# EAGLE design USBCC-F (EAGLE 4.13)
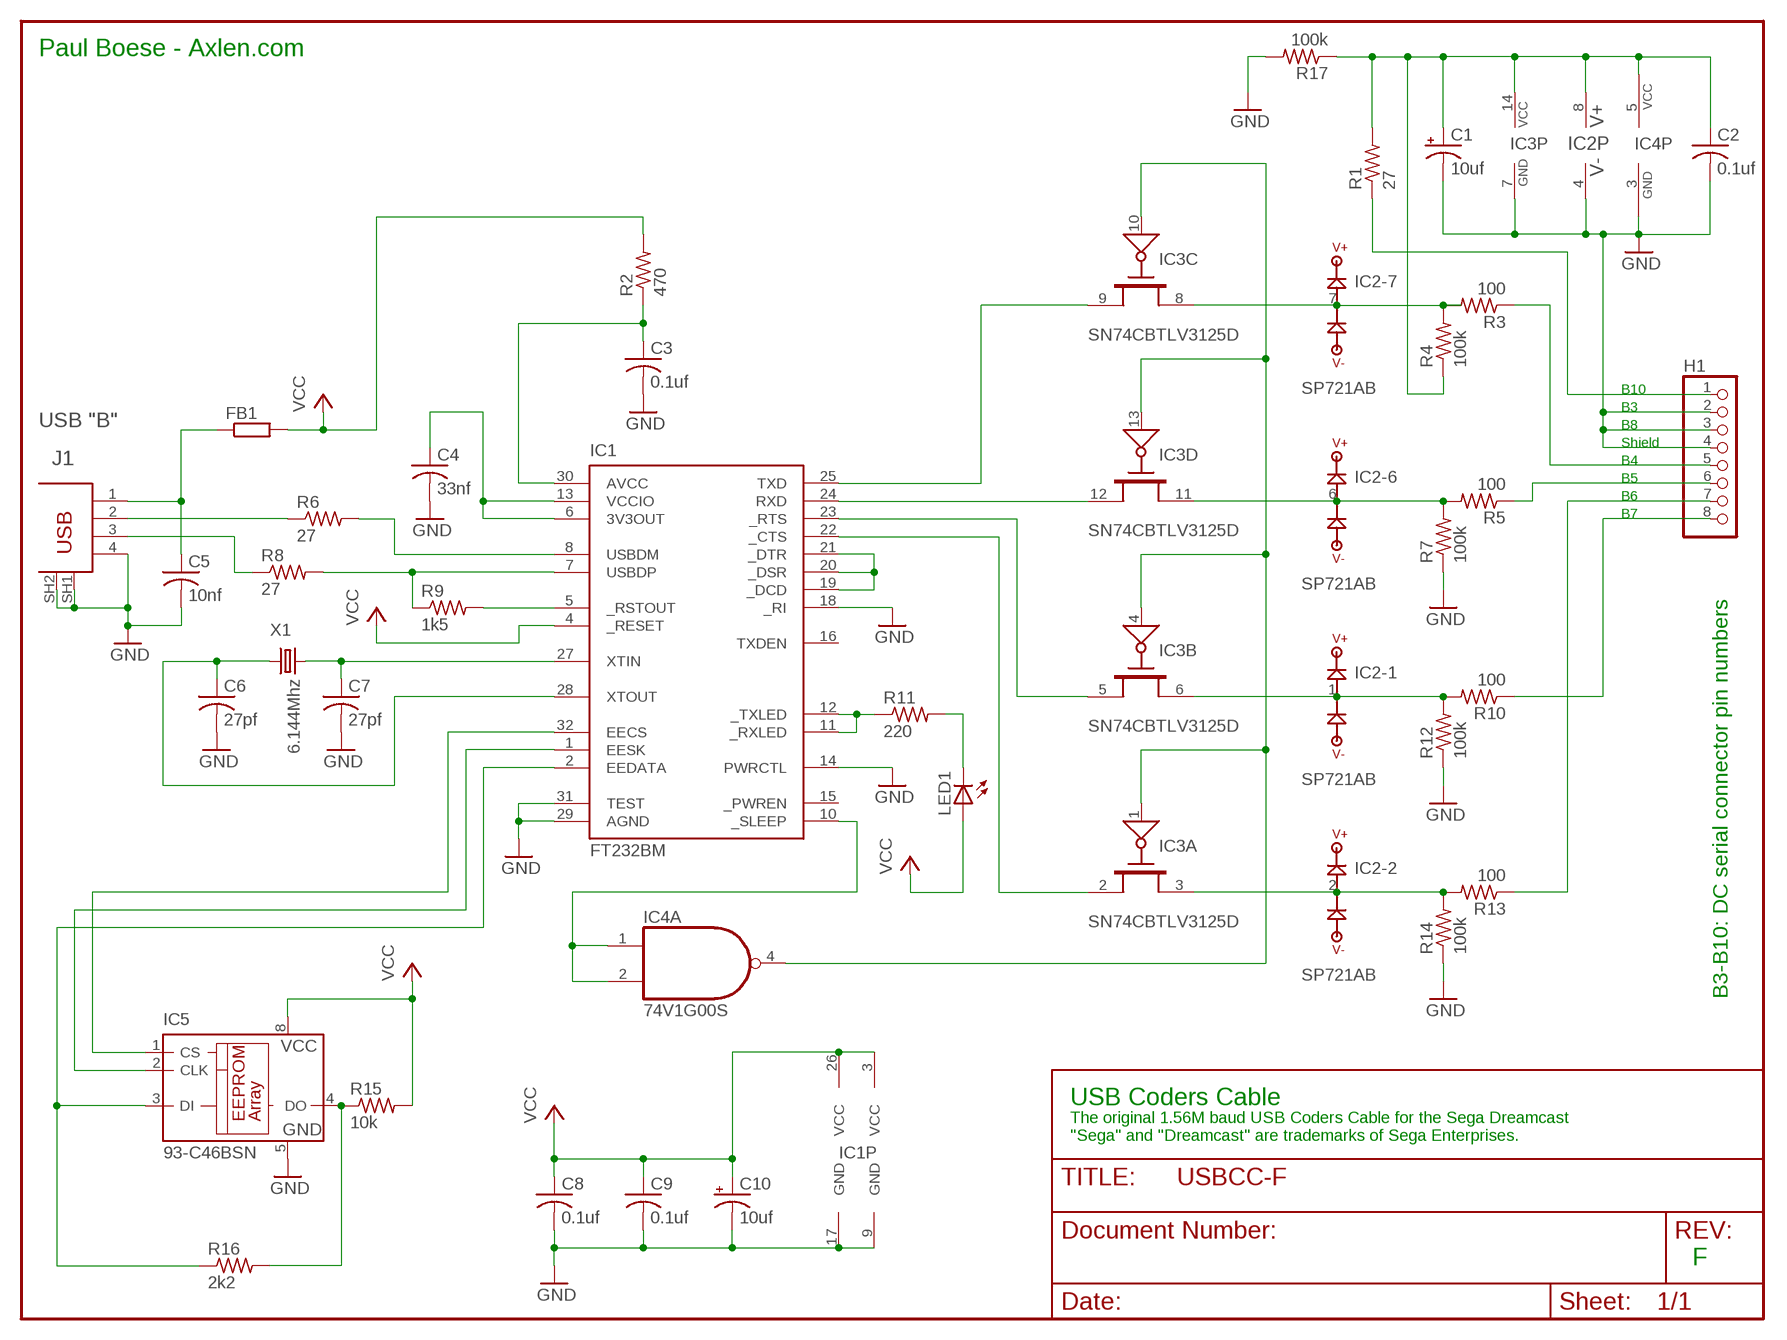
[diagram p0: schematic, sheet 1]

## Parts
C1  10uf  CPOL-USB/3528-21R  [B/3528-21R]
C2  0.1uf  C-USC0805  [C0805]
C3  0.1uf  C-USC0805  [C0805]
C4  33nf  C-USC0805  [C0805]
C5  10nf  C-USC0805  [C0805]
C6  27pf  C-USC0805  [C0805]
C7  27pf  C-USC0805  [C0805]
C8  0.1uf  C-USC0805  [C0805]
C9  0.1uf  C-USC0805  [C0805]
C10  10uf  CPOL-USB/3528-21R  [B/3528-21R]
FB1  R-EU_R0805  [R0805]
H1  PINHD-1X8  [1X08]
IC1  FT232BM  [LQFP-32]
IC2  SP721AB  [SO08]
IC3  SN74CBTLV3125D  74CBTLV125D  [SO14]
IC4  74V1G00S  [SOT23-5]
IC5  93-C46BSN  [SO-08]
J1  USB "B"  PN61729S  [PN61729]
LED1  LED5MM  [LED5MM]
R1  27  R-US_R0805  [R0805]
R2  470  R-US_R0805  [R0805]
R3  100  R-US_R0805  [R0805]
R4  100k  R-US_R0805  [R0805]
R5  100  R-US_R0805  [R0805]
R6  27  R-US_R0805  [R0805]
R7  100k  R-US_R0805  [R0805]
R8  27  R-US_R0805  [R0805]
R9  1k5  R-US_R0805  [R0805]
R10  100  R-US_R0805  [R0805]
R11  220  R-US_R1206  [R1206]
R12  100k  R-US_R0805  [R0805]
R13  100  R-US_R0805  [R0805]
R14  100k  R-US_R0805  [R0805]
R15  10k  R-US_R0805  [R0805]
R16  2k2  R-US_R0805  [R0805]
R17  100k  R-US_R0805  [R0805]
X1  6.144Mhz  CRYTALHC49U-V  [HC49U-V]

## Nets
GND: C1.- C2.2 C3.2 C4.2 C5.2 C6.2 C7.2 C8.2 C9.2 C10.- H1.2 H1.3 H1.4 IC1.9(GND) IC1.14(PWRCTL) IC1.17(GND) IC1.18(_RI) IC1.29(AGND) IC1.31(TEST) IC2.4(P:V-) IC3.7(P:GND) IC4.3(P:GND) IC5.5(GND) J1.4 J1.SH1 J1.SH2 R7.1 R12.1 R14.1 R17.2
N$2: J1.3 R8.1
N$3: IC1.7(USBDP) R8.2 R9.1
N$4: IC1.5(_RSTOUT) R9.2
N$5: IC1.8(USBDM) R6.2
N$6: C5.1 FB1.1 J1.1
N$7: C7.1 IC1.27(XTIN) X1.2
N$8: C3.1 IC1.30(AVCC) R2.1
N$9: C6.1 IC1.28(XTOUT) X1.1
N$10: IC1.24(RXD) IC3.12(D:I)
N$11: IC1.11(_RXLED) IC1.12(_TXLED) R11.1
N$13: IC5.4(DO) R15.1 R16.2
N$14: IC1.19(_DCD) IC1.20(_DSR) IC1.21(_DTR)
N$15: IC1.25(TXD) IC3.9(C:I)
N$17: C4.1 IC1.6(3V3OUT) IC1.13(VCCIO)
N$18: LED1.K(C) R11.2
N$19: IC1.2(EEDATA) IC5.3(DI) R16.1
N$20: IC1.23(_RTS) IC3.5(B:I)
N$21: IC1.22(_CTS) IC3.2(A:I)
N$22: C1.+ C2.1 IC2.8(P:V+) IC3.14(P:VCC) IC4.5(P:VCC) R1.2 R4.1 R17.1
N$24: IC2.7(-7:IN) IC3.8(C:O) R3.2 R4.2
N$26: IC2.6(-6:IN) IC3.11(D:O) R5.2 R7.2
N$27: H1.6 R5.1
N$28: H1.8 R10.1
N$29: H1.7 R13.1
N$32: H1.1 R1.1
N$34: H1.5 R3.1
N$35: IC2.1(-1:IN) IC3.6(B:O) R10.2 R12.2
N$36: IC2.2(-2:IN) IC3.3(A:O) R13.2 R14.2
N$37: IC1.1(EESK) IC5.2(CLK)
N$38: IC3.1(A:OE) IC3.4(B:OE) IC3.10(C:OE) IC3.13(D:OE) IC4.4(A:O)
N$39: IC1.32(EECS) IC5.1(CS)
N$40: IC1.10(_SLEEP) IC4.1(A:I0) IC4.2(A:I1)
N$41: J1.2 R6.1
VCC: C8.1 C9.1 C10.+ FB1.2 IC1.3(VCC) IC1.4(_RESET) IC1.26(VCC) IC5.8(VCC) LED1.A R2.2 R15.2
Unconnected: IC1.15(_PWREN) IC1.16(TXDEN) IC2.3(-3:IN) IC2.5(-5:IN)

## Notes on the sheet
- Paul Boese - Axlen.com
- B10
- B3
- B8
- Shield
- B4
- B5
- B6
- B7
- B3-B10: DC serial connector pin numbers
- USB Coders Cable
- The original 1.56M baud USB Coders Cable for the Sega Dreamcast
- "Sega" and "Dreamcast" are trademarks of Sega Enterprises.
- F

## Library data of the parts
C1 C10 = rcl:CPOL-US: POLARIZED CAPACITOR, American symbol
C2-C9 = rcl:C-US: CAPACITOR, American symbol
FB1 = rcl:R-EU_: RESISTOR, European symbol
H1 = pinhead:PINHD-1X8: PIN HEADER
IC1 = ftdi:FT232BM: USB UART 2nd Generation USB UART (USB <-> Serial)
IC2 = littelfuse:SP721: SP721 - TVS Diode Array Transient Voltage Suppressor 6 per package
IC3 = boese:74*125: Quad BUS SWITCH
IC4 = boese:74V1G00: Quad 2-input NAND gate
IC5 = microchip:93-*: Serial EEPROM 512 x 8 bit/256 x 16 bit/1 K/4 K, 5.0 V, Microwire
J1 = con-berg:PN61729S
LED1 = led:LED: LED
R1-R17 = rcl:R-US_: RESISTOR, American symbol
X1 = crystal:CRYTAL: CRYSTAL

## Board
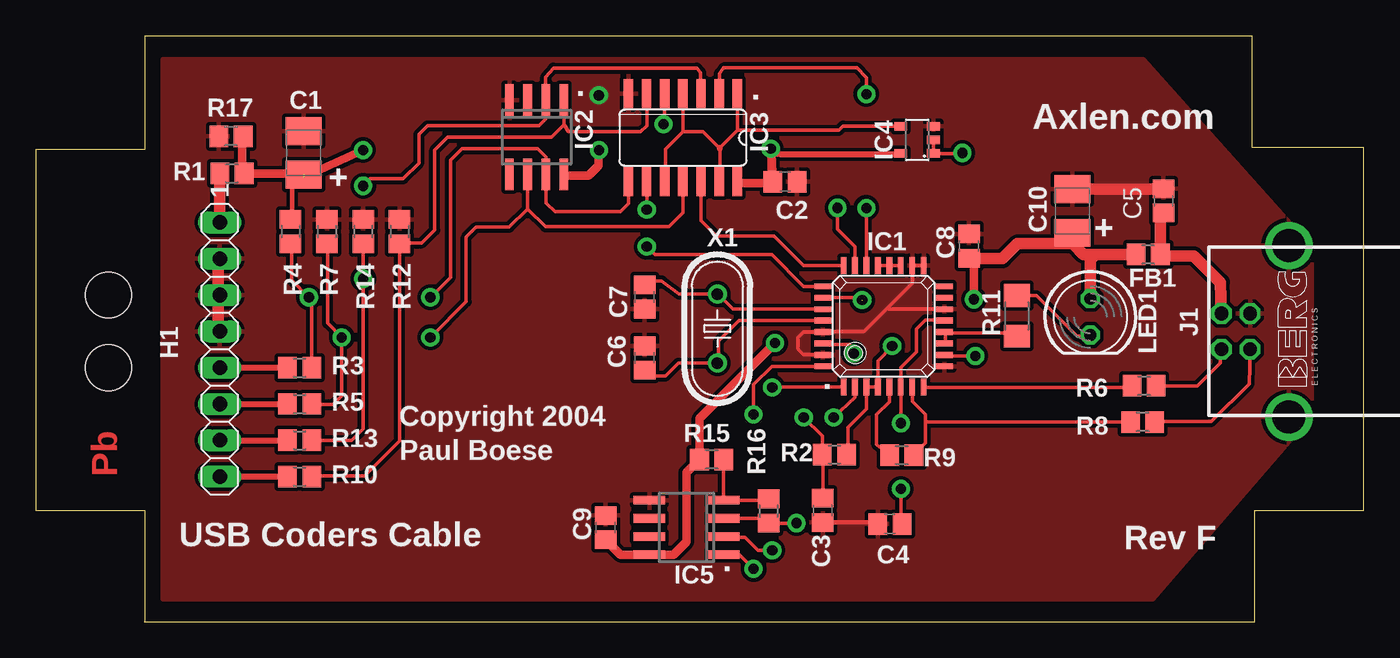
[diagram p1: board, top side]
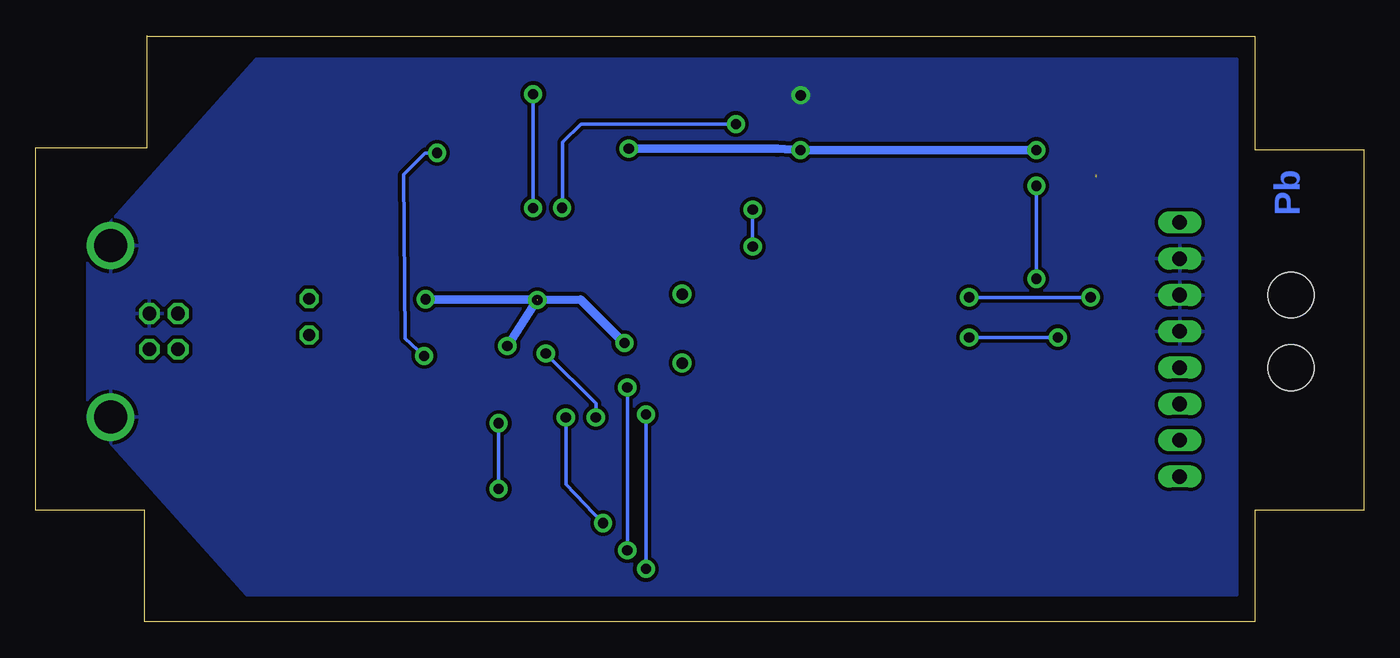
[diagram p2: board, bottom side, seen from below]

Size 92.87 x 41 mm. Coordinates in mm from the lower left corner, seen from the top.
Outline: 7.58,0 85.25,0 85.25,7.78 92.87,7.78 92.87,33.18 85.09,33.18 85.06,41
Outline: 85.06,40.96 7.62,40.96 7.62,33.02 0,33.02 0,7.78 7.62,7.78 7.62,0
Copper layers (1*16): Top 0.035mm / dielectric 1.5mm / Bottom 0.035mm
Design rules "default": minimum track width 10mil, minimum drill 28mil, track to track 10mil, track to pad 10mil, pad to pad 10mil, via to via 10mil, smd to smd 8mil, copper to edge 40mil, drill to drill 10mil, minimum pad ring 10mil, minimum via ring 8mil, stop-mask expansion 4mil, vias tented up to drill 0mil, thermal gap 10mil
Holes 3.2 mm at 5.08,22.86 5.08,17.78

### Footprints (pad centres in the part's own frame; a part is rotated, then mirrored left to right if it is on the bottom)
B/3528-21R = smd 1.95 x 2.5: + 1.525,0; - -1.525,0
C0805 = smd 1.3 x 1.5: 1 -0.85,0; 2 0.85,0
R0805 = smd 1.3 x 1.5: 1 -0.85,0; 2 0.85,0
1X08 = drill 1.016 long: 1 -8.89,0; 2 -6.35,0; 3 -3.81,0; 4 -1.27,0; 5 1.27,0; 6 3.81,0; 7 6.35,0; 8 8.89,0
LQFP-32 = smd 0.4 x 1.2: 1 -2.8,-4.25; 2 -2,-4.25; 3 -1.2,-4.25; 4 -0.4,-4.25; 5 0.4,-4.25; 6 1.2,-4.25; 7 2,-4.25; 8 2.8,-4.25; 17 2.8,4.25; 18 2,4.25; 19 1.2,4.25; 20 0.4,4.25; 21 -0.4,4.25; 22 -1.2,4.25; 23 -2,4.25; 24 -2.8,4.25 | smd 1.2 x 0.4: 9 4.25,-2.8; 10 4.25,-2; 11 4.25,-1.2; 12 4.25,-0.4; 13 4.25,0.4; 14 4.25,1.2; 15 4.25,2; 16 4.25,2.8; 25 -4.25,2.8; 26 -4.25,2; 27 -4.25,1.2; 28 -4.25,0.4; 29 -4.25,-0.4; 30 -4.25,-1.2; 31 -4.25,-2; 32 -4.25,-2.8
SO08 = smd 0.6 x 2.2: 1 -1.905,-2.6; 2 -0.635,-2.6; 3 0.635,-2.6; 4 1.905,-2.6; 5 1.905,2.6; 6 0.635,2.6; 7 -0.635,2.6; 8 -1.905,2.6
SO14 = smd 0.66 x 2.032: 1 -3.81,-3.073; 2 -2.54,-3.073; 3 -1.27,-3.073; 4 0,-3.073; 5 1.27,-3.073; 6 2.54,-3.073; 7 3.81,-3.073; 8 3.81,3.073; 9 2.54,3.073; 10 1.27,3.073; 11 0,3.073; 12 -1.27,3.073; 13 -2.54,3.073; 14 -3.81,3.073
SOT23-5 = smd 0.6 x 0.9: 1 -0.95,-1.15; 2 0,-1.15; 3 0.95,-1.15; 4 0.95,1.15; 5 -0.95,1.15
SO-08 = smd 0.6 x 2.2: 1 -1.905,-2.6; 2 -0.635,-2.6; 3 0.635,-2.6; 4 1.905,-2.6; 5 1.905,2.6; 6 0.635,2.6; 7 -0.635,2.6; 8 -1.905,2.6
PN61729 = drill 0.95 octagon: 1 1.25,4.71; 2 -1.25,4.71; 3 -1.25,2.71; 4 1.25,2.71 | drill 2.3 round: SH1 -6,0; SH2 6,0
LED5MM = drill 0.813 octagon: A -1.27,0; K 1.27,0
R1206 = smd 1.6 x 1.803: 1 -1.422,0; 2 1.422,0
HC49U-V = drill 0.813 round: 1 -2.413,0; 2 2.413,0

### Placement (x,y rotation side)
C1  18.73,32.81 270 top
C2  52.39,30.78 0 top
C3  55.04,7.8 270 top
C4  59.73,6.84 180 top
C5  78.87,29.45 90 top
C6  42.59,18.45 90 top
C7  42.59,22.73 270 top
C8  65.27,26.29 90 top
C9  39.86,6.59 90 top
C10  72.5,28.74 270 top
FB1  77.79,25.7 180 top
H1  12.87,19.05 270 top
IC1  59.3,20.67 0 top
IC2  35.03,33.91 180 top
IC3  45.25,33.86 180 top
IC4  61.63,33.72 90 top
IC5  45.51,6.6 90 top
J1  87.63,20.32 90 top
LED1  73.75,21.33 270 top
R1  13.72,31.37 0 top
R2  55.85,11.7 0 top
R3  18.45,17.78 0 top
R4  17.82,27.31 270 top
R5  18.45,15.24 0 top
R6  77.5,16.5 180 top
R7  20.36,27.31 270 top
R8  77.41,13.98 180 top
R9  60.56,11.65 180 top
R10  18.45,10.16 0 top
R11  68.6,21.4 90 top
R12  25.44,27.31 270 top
R13  18.45,12.7 0 top
R14  22.9,27.31 270 top
R15  47.27,11.36 180 top
R16  51.26,7.75 90 top
R17  13.65,33.97 180 top
X1  47.66,20.51 90 top

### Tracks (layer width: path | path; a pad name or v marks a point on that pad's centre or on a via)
GND  (via drill 0.71 pad 1.27)
  Top 0.254: 62.09,24.98 62.1,24.98 | 62.09,24.98 IC1.17 | 62.09,24.98 62.04,24.92 IC1.18 61.3,23.7 59.55,21.95 | 59.55,21.95 57.9,20.3 55,20.3 55.03,20.27 | 55.03,20.27 IC1.29 | IC1.14 59.63,21.87 59.55,21.95 | 55.03,20.27 53.67,20.27 53.3,19.9 53.3,19.1 53.7,18.7 55.06,18.7
  Top 0.305: 59.02,6.95 58.91,6.84 C4.2 | C3.2 59.02,6.95 | 59.02,6.95 59.05,6.99
  Top 0.813: H1.4 12.74,20.45 12.74,22.86 H1.3 12.74,22.99 12.74,25.4 H1.2 | C5.2 78.9,30.3 78.86,30.26 C10.-
  other vias: 39.37,36.83
  pour Bottom: 8.89,39.37 77.47,39.37 89.22,26.19 89.22,14.29 78.11,1.91 8.89,1.91
  pour Top: 8.89,39.37 8.89,1.59 78.11,1.59 89.22,14.45 89.22,26.19 77.47,39.37
N$2
  Top 0.254: J1.3 84.86,16.66 82.2,14 78.1,14 78.12,13.98 R8.1
N$3
  Top 0.254: IC1.7 61.3,15.41 62.2,14.5 62.2,14 | R9.1 61.41,11.69 61.4,11.7 62.2,12.5 62.2,14 | R8.2 62.22,13.98 62.2,14
N$4
  Top 0.254: IC1.5 59.7,15.4 58.8,14.5 58.8,12.4 59.75,11.65 | 59.75,11.65 59.8,11.6 | R9.2 59.75,11.65
N$5
  Top 0.254: IC1.8 62.09,16.41 62.1,16.4 76.55,16.4 R6.2
N$6
  Top 0.813: C5.1 78.87,28.53 78.64,28.3 FB1.1 78.64,25.66 78.7,25.6 81,25.6 82.86,23.75 J1.1
N$7
  Top 0.254: IC1.27 48.76,21.87 47.67,22.96 47.66,22.96 X1.2 45,22.92 43.76,23.84 42.6,23.84 42.54,23.9 | 42.54,23.9 42.51,23.93 | C7.1 42.54,23.9
N$8  (via drill 0.71 pad 1.27)
  Top 0.254: C3.1 55.04,11.76 55,11.8 R2.1 55,13 v53.7,14.3 | v57.2,18.78 57.2,19.1 56.9,19.4 55,19.4 55.05,19.45 IC1.30
  Bottom 0.254: v53.7,14.3 53.7,15.28 v57.2,18.78
N$9
  Top 0.254: IC1.28 49.19,21.07 47.76,19.64 47.76,18.28 47.63,18.15 47.66,18.12 X1.1 44.95,18.1 44.04,17.19 42.72,17.19 42.65,17.12 C6.1
N$10
  Top 0.254: IC1.24 53.68,24.92 51.61,26.99 47.62,26.99 46.53,28.08 46.53,30.84 46.52,30.85 | 46.52,30.85 46.4,30.97 | 46.52,30.85 IC3.12
N$11
  Top 0.254: R11.1 68.38,20.2 63.5,20.2 63.5,20.23 IC1.12 63.6,20.22 63.6,19.5 63.58,19.5 IC1.11
N$13
  Top 0.254: 51.3,8.6 | 51.3,8.6 R16.2 | 51.3,8.6 51.21,8.51 IC5.4 48.11,11.41 48.12,11.42 | 48.12,11.42 48.2,11.5 | 48.12,11.42 R15.1
N$14
  Top 0.254: IC1.20 59.77,24.92 59.78,24.93 | IC1.20 IC1.21 | IC1.19 60.48,24.93 IC1.20
N$15  (via drill 0.71 pad 1.27)
  Top 0.254: IC1.25 53.68,23.47 51.47,25.68 43.29,25.68 v42.73,26.24 | IC3.9 42.71,30.86 42.73,30.88 v42.73,28.83
  Bottom 0.254: v42.73,26.24 v42.73,28.83
N$17  (via drill 0.71 pad 1.27)
  Top 0.254: v60.5,13.9 v60.49,13.91 IC1.6 60.49,17.79 61.59,18.89 61.59,20.48 62.23,21.11 63.5,21.11 IC1.13 | C4.1 60.54,6.84 60.5,6.8 v60.5,9.3
  Bottom 0.254: v60.5,9.3 v60.5,13.9
N$18
  Top 0.254: R11.2 69.98,22.82 72.8,20 73.6,20 73.7,20.1 73.74,20.06 LED1.K
N$19  (via drill 0.71 pad 1.27)
  Top 0.254: IC5.3 50.86,7.24 51.2,6.9 R16.1 51.3,6.9 v53.2,6.9 | IC1.2 57.3,15.7 v55.8,14.3
  Bottom 0.254: v55.8,14.3 55.8,9.6 v53.2,6.9
N$20  (via drill 0.71 pad 1.27)
  Top 0.254: IC3.5 43.98,34.89 v43.91,34.82 | v56.07,28.96 56.07,27.46 57.29,26.24 57.29,24.98 57.34,24.93 57.33,24.92 IC1.23
  Bottom 0.254: v43.91,34.82 54.75,34.82 56.02,33.55 56.02,29.01 v56.07,28.96
N$21  (via drill 0.71 pad 1.27)
  Top 0.254: IC1.22 58.09,28.34 v58.08,28.95 | v58.08,36.92 58.08,38.06 57.44,38.76 48.1,38.76 47.8,38.36 47.8,36.83 47.79,36.84 IC3.2
  Bottom 0.254: v58.08,28.95 v58.08,36.92
N$22  (via drill 0.71 pad 1.27)  (1 unrouted)
  Top 0.305: R4.1 17.94,28.16 17.94,31.37
  Top 0.406: 51.44,32.74 52.1,32.7 60.5,32.7 60.48,32.72 IC4.5
  Top 0.61: v51.4,33.1 51.5,30.7 49.15,30.7 IC3.14 | IC2.8 37.04,31.2 38.66,31.2 39.37,31.91 v39.4,33 | C2.1 51.44,32.74 | 18.73,31.12 v22.89,33 | 14.45,31.37 14.45,31.27 | 14.45,31.37 R1.2 17.94,31.37 18.73,31.37 | R17.1 14.45,33.97 14.45,31.37 | 18.73,31.37 C1.+ | 18.73,31.37 18.73,31.43
  Top 0.813: 51.5,30.8 51.52,30.8 C2.1 51.5,30.74 51.5,30.7 51.5,30.8
  Bottom 0.61: v22.89,33 36.07,33 v39.4,33 41,33.1 v51.4,33.1
N$24  (via drill 0.71 pad 1.27)
  Top 0.254: IC3.8 41.44,29.24 40.9,28.7 36.3,28.7 35.7,29.3 | IC2.7 35.61,31.31 35.6,31.3 35.7,31.2 35.7,29.3 | 35.7,29.3 35.7,32.5 35.1,33.1 29.8,33.1 29,32.3 29,24.1 v27.6,22.7 | R4.2 17.86,26.5 17.9,26.5 17.9,23.9 v19.1,22.7 19.3,22.5 R3.2
  Top 0.406: R4.2 17.82,26.67
  Bottom 0.254: v19.1,22.7 v27.6,22.7
N$26  (via drill 0.71 pad 1.27)
  Top 0.254: 34.39,28.89 IC2.6 | 34.39,28.89 35.64,27.64 44.29,27.64 45.26,28.61 IC3.11 | 34.39,28.89 33.1,27.6 30.8,27.6 30.1,26.9 30.1,22.4 v27.6,19.9 | R7.2 20.4,26.42 20.4,20.9 v21.4,19.9 21.4,15.8 20.8,15.2 19.3,15.2 19.26,15.24 | 19.26,15.24 19.2,15.3 | 19.26,15.24 R5.2
  Top 0.406: R7.2 20.36,26.67 | IC3.11 45.31,30.84
  Bottom 0.254: v21.4,19.9 v27.6,19.9
N$27
  Top 0.406: 17.82,15.24 R5.1 H1.6
N$28
  Top 0.406: 17.82,10.16 R10.1 H1.8
N$29
  Top 0.406: 17.82,12.7 R13.1 H1.7
N$32
  Top 0.813: R1.1 12.86,31.43 | R1.1 | H1.1 R1.1
N$34
  Top 0.406: 17.82,17.78 R3.1 H1.5
N$35
  Top 0.254: 36.93,34.76 IC2.1 | 36.93,34.76 37.26,34.28 42.31,34.28 42.73,34.7 42.73,36.92 IC3.6 | IC3.6 42.64,37.01 | IC3.6 | 36.93,34.76 36.07,33.9 28.8,33.9 27.9,33 27.9,27.4 27,26.5 25.4,26.5 R12.2 25.44,12.64 23,10.2 19.2,10.2 19.24,10.16 R10.2
  Top 0.406: R12.2 25.44,26.67
N$36  (via drill 0.71 pad 1.27)
  Top 0.254: 46.49,36.83 46.49,38.42 46.23,38.74 36.2,38.74 35.66,38.1 IC2.2 35.66,35.16 35.2,34.7 27.4,34.7 26.8,34.1 26.8,32.1 25.7,31 23.4,31 v22.9,30.5 | 22.9,26.6 v22.9,24 22.9,13.5 22.1,12.7 R13.2 19.1,12.7
  Top 0.406: R14.2 22.9,26.6 22.9,26.67 | 46.52,36.8 46.53,36.79 | 46.52,36.8 IC3.3 | 46.49,36.83 46.52,36.8
  Bottom 0.254: v22.9,24 v22.9,30.5
N$37  (via drill 0.71 pad 1.27)
  Top 0.254: IC1.1 51.99,16.42 v51.5,16.4 | v51.5,5 50.5,5 49.6,5.9 48.2,5.9 48.1,6 IC5.2
  Bottom 0.254: v51.5,5 v51.5,16.4
N$38
  Top 0.254: 49.06,34.38 IC3.1 | 47.84,33.16 49.06,34.38 | 47.84,30.75 47.84,33.11 46.67,34.28 45.25,34.28 | 45.25,34.28 IC3.4 | 45.25,34.28 44.04,33.07 44.04,30.8 | 49.06,34.38 56.15,34.38 56.46,34.69 60.49,34.69
  Top 0.406: 47.84,30.75 47.8,30.79 IC3.13 | 47.84,33.11 47.84,33.16 | IC3.10 43.98,30.76 43.99,30.75 44.04,30.8 | IC4.4 60.48,34.69 60.49,34.69 60.53,34.73
N$39  (via drill 0.71 pad 1.27)
  Top 0.254: IC1.32 51.47,17.87 50.2,16.6 v50.2,14.5 | IC5.1 47.9,4.7 | IC5.1 | v50.2,3.7 49.2,4.7 IC5.1
  Bottom 0.254: v50.2,3.7 v50.2,14.5
N$40  (via drill 0.71 pad 1.27)
  Top 0.254: 62.82,33.72 62.9,33.8 | 62.82,33.72 IC4.2 | 62.82,33.72 62.78,33.69 IC4.1 64.77,32.77 v64.8,32.8 | 63.53,18.67 63.5,18.7 | IC1.10 63.53,18.67 | v65.7,18.6 63.6,18.6 63.53,18.67
  Bottom 0.254: v64.8,32.8 65.62,32.8 67.15,31.27 67.02,19.82 v65.7,18.6
N$41
  Top 0.254: J1.2 82.86,18.12 81.23,16.5 78.5,16.5 78.4,16.4 78.36,16.45 R6.1
VCC  (via drill 0.71 pad 1.27)  (1 unrouted)
  Top 0.254: IC1.3 58,16.5 | IC1.3 IC1.4 58.9,18.26 59.89,19.25 v59.89,19.3 | IC1.3 58.09,14.9 56.8,13.6 56.8,11.9 56.7,11.8 R2.2 | IC1.26 57.63,22.67 v57.8,22.5 | C9.1 | IC5.8 | 65.58,22.56 65.56,22.54 | v65.61,22.56 65.58,22.56 | 65.58,22.56 65.6,22.58
  Top 0.61: v51.7,19.5 46.42,14.22 R15.2 45.5,10.44 45.5,5.6 44.6,4.7 IC5.8 40.9,4.7 C9.1 | 65.6,22.58 65.6,25.4
  Top 0.813: 72.51,26.46 73.27,25.7 FB1.2 74.11,25.7 73.74,25.33 73.74,22.66 73.8,22.6 | C10.+ 72.5,27.17 72.51,27.16 72.51,26.46 | 73.8,22.6 73.87,22.53 | 73.8,22.6 LED1.A | 72.51,26.46 68.66,26.46 67.6,25.4 65.6,25.4 65.5,25.5 65.44,25.44 C8.1
  Bottom 0.254: v57.8,22.5 57.8,22.53 57.78,22.54 57.8,22.56
  Bottom 0.406: v51.7,19.5 51.73,19.5
  Bottom 0.61: 51.73,19.5 54.77,22.54 57.78,22.52 | v59.89,19.3 v57.8,22.5 | 57.8,22.56 v65.61,22.56

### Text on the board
Top: Pb
Bottom: Pb
tNames: . | . | Axlen.com | 1 | + | + | . | Copyright 2004 | Paul Boese | USB Coders Cable | Rev F | .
